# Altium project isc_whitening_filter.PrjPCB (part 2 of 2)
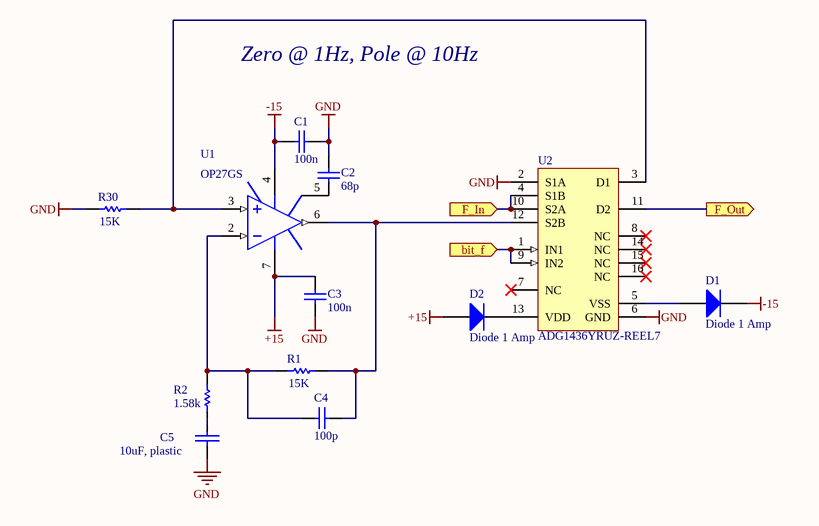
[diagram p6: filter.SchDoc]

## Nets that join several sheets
+15: white_top (25 pins), 24dB_a (C26_24dB_a.2 D7_24dB_a.1 U9_24dB_a.7), 12dB_a (C26_12dB_a.2 D7_12dB_a.1 U9_12dB_a.7), 6dB_a (C26_6dB_a.2 D7_6dB_a.1 U9_6dB_a.7), 3dB_a (C26_3dB_a.2 D7_3dB_a.1 U9_3dB_a.7), U_diff_in_A (C28_U_diff_in_A.1 U10_U_diff_in_A.4), U_diff_out_A (C30_U_diff_out_A.1 U11_U_diff_out_A.8), U_logic_A (U14_U_logic_A.13 U15_U_logic_A.13), U_diff_in_B (C28_U_diff_in_B.1 U10_U_diff_in_B.4), U_diff_out_B (C30_U_diff_out_B.1 U11_U_diff_out_B.8), U_logic_B (U14_U_logic_B.13 U15_U_logic_B.13), U_diff_in_C (C28_U_diff_in_C.1 U10_U_diff_in_C.4), U_diff_out_C (C30_U_diff_out_C.1 U11_U_diff_out_C.8), U_logic_C (U14_U_logic_C.13 U15_U_logic_C.13), U_diff_in_D (C28_U_diff_in_D.1 U10_U_diff_in_D.4), U_diff_out_D (C30_U_diff_out_D.1 U11_U_diff_out_D.8), U_logic_D (U14_U_logic_D.13 U15_U_logic_D.13), 24dB_b (C26_24dB_b.2 D7_24dB_b.1 U9_24dB_b.7), 12dB_b (C26_12dB_b.2 D7_12dB_b.1 U9_12dB_b.7), 12dB_c (C26_12dB_c.2 D7_12dB_c.1 U9_12dB_c.7), 12dB_d (C26_12dB_d.2 D7_12dB_d.1 U9_12dB_d.7), 24dB_c (C26_24dB_c.2 D7_24dB_c.1 U9_24dB_c.7), 24dB_d (C26_24dB_d.2 D7_24dB_d.1 U9_24dB_d.7), 6dB_b (C26_6dB_b.2 D7_6dB_b.1 U9_6dB_b.7), 6dB_c (C26_6dB_c.2 D7_6dB_c.1 U9_6dB_c.7), 6dB_d (C26_6dB_d.2 D7_6dB_d.1 U9_6dB_d.7), 3dB_b (C26_3dB_b.2 D7_3dB_b.1 U9_3dB_b.7), 3dB_c (C26_3dB_c.2 D7_3dB_c.1 U9_3dB_c.7), 3dB_d (C26_3dB_d.2 D7_3dB_d.1 U9_3dB_d.7), PZ1_b (C3_PZ1_b.2 D2_PZ1_b.1 U1_PZ1_b.7), PZ2_b (C3_PZ2_b.2 D2_PZ2_b.1 U1_PZ2_b.7), PZ3_b (C3_PZ3_b.2 D2_PZ3_b.1 U1_PZ3_b.7), PZ1_a (C3_PZ1_a.2 D2_PZ1_a.1 U1_PZ1_a.7), PZ2_a (C3_PZ2_a.2 D2_PZ2_a.1 U1_PZ2_a.7), PZ3_a (C3_PZ3_a.2 D2_PZ3_a.1 U1_PZ3_a.7), PZ1_c (C3_PZ1_c.2 D2_PZ1_c.1 U1_PZ1_c.7), PZ2_c (C3_PZ2_c.2 D2_PZ2_c.1 U1_PZ2_c.7), PZ3_c (C3_PZ3_c.2 D2_PZ3_c.1 U1_PZ3_c.7), PZ1_d (C3_PZ1_d.2 D2_PZ1_d.1 U1_PZ1_d.7), PZ2_d (C3_PZ2_d.2 D2_PZ2_d.1 U1_PZ2_d.7), PZ3_d (C3_PZ3_d.2 D2_PZ3_d.1 U1_PZ3_d.7)
-15: white_top (16 pins), 24dB_a (C24_24dB_a.2 D6_24dB_a.2 U9_24dB_a.4), 12dB_a (C24_12dB_a.2 D6_12dB_a.2 U9_12dB_a.4), 6dB_a (C24_6dB_a.2 D6_6dB_a.2 U9_6dB_a.4), 3dB_a (C24_3dB_a.2 D6_3dB_a.2 U9_3dB_a.4), U_diff_in_A (C29_U_diff_in_A.1 U10_U_diff_in_A.13), U_diff_out_A (C31_U_diff_out_A.1 U11_U_diff_out_A.4), U_logic_A (C32_U_logic_A.2 C36_U_logic_A.2 U14_U_logic_A.4 U15_U_logic_A.4), U_diff_in_B (C29_U_diff_in_B.1 U10_U_diff_in_B.13), U_diff_out_B (C31_U_diff_out_B.1 U11_U_diff_out_B.4), U_logic_B (C32_U_logic_B.2 C36_U_logic_B.2 U14_U_logic_B.4 U15_U_logic_B.4), U_diff_in_C (C29_U_diff_in_C.1 U10_U_diff_in_C.13), U_diff_out_C (C31_U_diff_out_C.1 U11_U_diff_out_C.4), U_logic_C (C32_U_logic_C.2 C36_U_logic_C.2 U14_U_logic_C.4 U15_U_logic_C.4), U_diff_in_D (C29_U_diff_in_D.1 U10_U_diff_in_D.13), U_diff_out_D (C31_U_diff_out_D.1 U11_U_diff_out_D.4), U_logic_D (C32_U_logic_D.2 C36_U_logic_D.2 U14_U_logic_D.4 U15_U_logic_D.4), 24dB_b (C24_24dB_b.2 D6_24dB_b.2 U9_24dB_b.4), 12dB_b (C24_12dB_b.2 D6_12dB_b.2 U9_12dB_b.4), 12dB_c (C24_12dB_c.2 D6_12dB_c.2 U9_12dB_c.4), 12dB_d (C24_12dB_d.2 D6_12dB_d.2 U9_12dB_d.4), 24dB_c (C24_24dB_c.2 D6_24dB_c.2 U9_24dB_c.4), 24dB_d (C24_24dB_d.2 D6_24dB_d.2 U9_24dB_d.4), 6dB_b (C24_6dB_b.2 D6_6dB_b.2 U9_6dB_b.4), 6dB_c (C24_6dB_c.2 D6_6dB_c.2 U9_6dB_c.4), 6dB_d (C24_6dB_d.2 D6_6dB_d.2 U9_6dB_d.4), 3dB_b (C24_3dB_b.2 D6_3dB_b.2 U9_3dB_b.4), 3dB_c (C24_3dB_c.2 D6_3dB_c.2 U9_3dB_c.4), 3dB_d (C24_3dB_d.2 D6_3dB_d.2 U9_3dB_d.4), PZ1_b (C1_PZ1_b.2 D1_PZ1_b.2 U1_PZ1_b.4), PZ2_b (C1_PZ2_b.2 D1_PZ2_b.2 U1_PZ2_b.4), PZ3_b (C1_PZ3_b.2 D1_PZ3_b.2 U1_PZ3_b.4), PZ1_a (C1_PZ1_a.2 D1_PZ1_a.2 U1_PZ1_a.4), PZ2_a (C1_PZ2_a.2 D1_PZ2_a.2 U1_PZ2_a.4), PZ3_a (C1_PZ3_a.2 D1_PZ3_a.2 U1_PZ3_a.4), PZ1_c (C1_PZ1_c.2 D1_PZ1_c.2 U1_PZ1_c.4), PZ2_c (C1_PZ2_c.2 D1_PZ2_c.2 U1_PZ2_c.4), PZ3_c (C1_PZ3_c.2 D1_PZ3_c.2 U1_PZ3_c.4), PZ1_d (C1_PZ1_d.2 D1_PZ1_d.2 U1_PZ1_d.4), PZ2_d (C1_PZ2_d.2 D1_PZ2_d.2 U1_PZ2_d.4), PZ3_d (C1_PZ3_d.2 D1_PZ3_d.2 U1_PZ3_d.4)
GND: white_top (38 pins), 24dB_a (7 pins), 12dB_a (7 pins), 6dB_a (7 pins), 3dB_a (7 pins), U_diff_in_A (7 pins), U_diff_out_A (C30_U_diff_out_A.2 C31_U_diff_out_A.2 U11_U_diff_out_A.5), U_logic_A (15 pins), U_diff_in_B (7 pins), U_diff_out_B (C30_U_diff_out_B.2 C31_U_diff_out_B.2 U11_U_diff_out_B.5), U_logic_B (15 pins), U_diff_in_C (7 pins), U_diff_out_C (C30_U_diff_out_C.2 C31_U_diff_out_C.2 U11_U_diff_out_C.5), U_logic_C (15 pins), U_diff_in_D (7 pins), U_diff_out_D (C30_U_diff_out_D.2 C31_U_diff_out_D.2 U11_U_diff_out_D.5), U_logic_D (15 pins), 24dB_b (7 pins), 12dB_b (7 pins), 12dB_c (7 pins), 12dB_d (7 pins), 24dB_c (7 pins), 24dB_d (7 pins), 6dB_b (7 pins), 6dB_c (7 pins), 6dB_d (7 pins), 3dB_b (7 pins), 3dB_c (7 pins), 3dB_d (7 pins), PZ1_b (7 pins), PZ2_b (7 pins), PZ3_b (7 pins), PZ1_a (7 pins), PZ2_a (7 pins), PZ3_a (7 pins), PZ1_c (7 pins), PZ2_c (7 pins), PZ3_c (7 pins), PZ1_d (7 pins), PZ2_d (7 pins), PZ3_d (7 pins)
VCC: white_top (5 pins), U_logic_A (5 pins), U_logic_B (5 pins), U_logic_C (5 pins), U_logic_D (5 pins)
A1: 24dB_a (U8_24dB_a.1 U8_24dB_a.9), U_logic_A (U13_U_logic_A.19 U14_U_logic_A.1)
A2: 12dB_a (U8_12dB_a.1 U8_12dB_a.9), U_logic_A (U13_U_logic_A.18 U14_U_logic_A.16)
A3: 6dB_a (U8_6dB_a.1 U8_6dB_a.9), U_logic_A (U13_U_logic_A.17 U14_U_logic_A.9)
A4: 3dB_a (U8_3dB_a.1 U8_3dB_a.9), U_logic_A (U13_U_logic_A.16 U14_U_logic_A.8)
A5: U_logic_A (U13_U_logic_A.15 U15_U_logic_A.1), PZ1_a (U2_PZ1_a.1 U2_PZ1_a.9)
A6: U_logic_A (U13_U_logic_A.14 U15_U_logic_A.16), PZ2_a (U2_PZ2_a.1 U2_PZ2_a.9)
A7: U_logic_A (U13_U_logic_A.13 U15_U_logic_A.9), PZ3_a (U2_PZ3_a.1 U2_PZ3_a.9)
AN_1: white_top (IN1.2 J5.9), U_diff_in_A (R22_U_diff_in_A.1 R33_U_diff_in_A.2)
AN_2: white_top (IN2.2 J5.10), U_diff_in_B (R22_U_diff_in_B.1 R33_U_diff_in_B.2)
AN_3: white_top (IN3.2 J5.11), U_diff_in_C (R22_U_diff_in_C.1 R33_U_diff_in_C.2)
AN_4: white_top (IN4.2 J5.12), U_diff_in_D (R22_U_diff_in_D.1 R33_U_diff_in_D.2)
AP_1: white_top (IN1.1 J5.1), U_diff_in_A (R14_U_diff_in_A.2 R32_U_diff_in_A.2)
AP_2: white_top (IN2.1 J5.2), U_diff_in_B (R14_U_diff_in_B.2 R32_U_diff_in_B.2)
AP_3: white_top (IN3.1 J5.3), U_diff_in_C (R14_U_diff_in_C.2 R32_U_diff_in_C.2)
AP_4: white_top (IN4.1 J5.4), U_diff_in_D (R14_U_diff_in_D.2 R32_U_diff_in_D.2)
B1: U_logic_B (U13_U_logic_B.19 U14_U_logic_B.1), 24dB_b (U8_24dB_b.1 U8_24dB_b.9)
B2: U_logic_B (U13_U_logic_B.18 U14_U_logic_B.16), 12dB_b (U8_12dB_b.1 U8_12dB_b.9)
B3: U_logic_B (U13_U_logic_B.17 U14_U_logic_B.9), 6dB_b (U8_6dB_b.1 U8_6dB_b.9)
B4: U_logic_B (U13_U_logic_B.16 U14_U_logic_B.8), 3dB_b (U8_3dB_b.1 U8_3dB_b.9)
B5: U_logic_B (U13_U_logic_B.15 U15_U_logic_B.1), PZ1_b (U2_PZ1_b.1 U2_PZ1_b.9)
B6: U_logic_B (U13_U_logic_B.14 U15_U_logic_B.16), PZ2_b (U2_PZ2_b.1 U2_PZ2_b.9)
B7: U_logic_B (U13_U_logic_B.13 U15_U_logic_B.9), PZ3_b (U2_PZ3_b.1 U2_PZ3_b.9)
BI_0: white_top (P1.2 P2.3), U_logic_A (R29_U_logic_A.3 U13_U_logic_A.2)
BI_1: white_top (P1.3 P2.5), U_logic_A (R29_U_logic_A.4 U13_U_logic_A.3)
BI_2: white_top (P1.4 P2.7), U_logic_A (R29_U_logic_A.5 U13_U_logic_A.4)
BI_3: white_top (P1.5 P2.9), U_logic_A (R29_U_logic_A.6 U13_U_logic_A.5)
BI_4: white_top (P1.6 P2.11), U_logic_A (R29_U_logic_A.7 U13_U_logic_A.6)
BI_5: white_top (P1.7 P2.13), U_logic_A (R29_U_logic_A.8 U13_U_logic_A.7)
BI_6: white_top (P1.8 P2.15), U_logic_A (R29_U_logic_A.9 U13_U_logic_A.8)
BI_7: white_top (P1.9 P2.17), U_logic_A (R29_U_logic_A.2 U13_U_logic_A.11 U15_U_logic_A.8)
BI_8: white_top (P1.10 P2.19), U_logic_B (R29_U_logic_B.3 U13_U_logic_B.2)
BI_9: white_top (P1.11 P2.21), U_logic_B (R29_U_logic_B.4 U13_U_logic_B.3)
BI_10: white_top (P1.12 P2.23), U_logic_B (R29_U_logic_B.5 U13_U_logic_B.4)
BI_11: white_top (P1.13 P2.25), U_logic_B (R29_U_logic_B.6 U13_U_logic_B.5)
BI_12: white_top (P1.14 P2.27), U_logic_B (R29_U_logic_B.7 U13_U_logic_B.6)
BI_13: white_top (P1.15 P2.29), U_logic_B (R29_U_logic_B.8 U13_U_logic_B.7)
BI_14: white_top (P1.16 P2.31), U_logic_B (R29_U_logic_B.9 U13_U_logic_B.8)
BI_15: white_top (P1.17 P2.33), U_logic_B (R29_U_logic_B.2 U13_U_logic_B.11 U15_U_logic_B.8)
BI_16: white_top (P1.21 P2.4), U_logic_C (R29_U_logic_C.3 U13_U_logic_C.2)
BI_17: white_top (P1.22 P2.6), U_logic_C (R29_U_logic_C.4 U13_U_logic_C.3)
BI_18: white_top (P1.23 P2.8), U_logic_C (R29_U_logic_C.5 U13_U_logic_C.4)
BI_19: white_top (P1.24 P2.10), U_logic_C (R29_U_logic_C.6 U13_U_logic_C.5)
BI_20: white_top (P1.25 P2.12), U_logic_C (R29_U_logic_C.7 U13_U_logic_C.6)
BI_21: white_top (P1.26 P2.14), U_logic_C (R29_U_logic_C.8 U13_U_logic_C.7)
BI_22: white_top (P1.27 P2.16), U_logic_C (R29_U_logic_C.9 U13_U_logic_C.8)
BI_23: white_top (P1.28 P2.18), U_logic_C (R29_U_logic_C.2 U13_U_logic_C.11 U15_U_logic_C.8)
BI_24: white_top (P1.29 P2.20), U_logic_D (R29_U_logic_D.3 U13_U_logic_D.2)
BI_25: white_top (P1.30 P2.22), U_logic_D (R29_U_logic_D.4 U13_U_logic_D.3)
BI_26: white_top (P1.31 P2.24), U_logic_D (R29_U_logic_D.5 U13_U_logic_D.4)
BI_27: white_top (P1.32 P2.26), U_logic_D (R29_U_logic_D.6 U13_U_logic_D.5)
BI_28: white_top (P1.33 P2.28), U_logic_D (R29_U_logic_D.7 U13_U_logic_D.6)
BI_29: white_top (P1.34 P2.30), U_logic_D (R29_U_logic_D.8 U13_U_logic_D.7)
BI_30: white_top (P1.35 P2.32), U_logic_D (R29_U_logic_D.9 U13_U_logic_D.8)
BI_31: white_top (P1.36 P2.34), U_logic_D (R29_U_logic_D.2 U13_U_logic_D.11 U15_U_logic_D.8)
BO_0: white_top (P3.2), U_logic_A (R31_U_logic_A.16)
BO_1: white_top (P3.3), U_logic_A (R31_U_logic_A.15)
BO_2: white_top (P3.4), U_logic_A (R31_U_logic_A.14)
BO_3: white_top (P3.5), U_logic_A (R31_U_logic_A.13)
BO_4: white_top (P3.6), U_logic_A (R31_U_logic_A.12)
BO_5: white_top (P3.7), U_logic_A (R31_U_logic_A.11)
BO_6: white_top (P3.8), U_logic_A (R31_U_logic_A.10)
BO_7: white_top (P3.9), U_logic_A (R31_U_logic_A.9)
BO_8: white_top (P3.10), U_logic_B (R31_U_logic_B.16)
BO_9: white_top (P3.11), U_logic_B (R31_U_logic_B.15)
BO_10: white_top (P3.12), U_logic_B (R31_U_logic_B.14)
BO_11: white_top (P3.13), U_logic_B (R31_U_logic_B.13)
BO_12: white_top (P3.14), U_logic_B (R31_U_logic_B.12)
BO_13: white_top (P3.15), U_logic_B (R31_U_logic_B.11)
BO_14: white_top (P3.16), U_logic_B (R31_U_logic_B.10)
BO_15: white_top (P3.17), U_logic_B (R31_U_logic_B.9)
BO_16: white_top (P3.21), U_logic_C (R31_U_logic_C.16)
BO_17: white_top (P3.22), U_logic_C (R31_U_logic_C.15)
BO_18: white_top (P3.23), U_logic_C (R31_U_logic_C.14)
BO_19: white_top (P3.24), U_logic_C (R31_U_logic_C.13)
BO_20: white_top (P3.25), U_logic_C (R31_U_logic_C.12)
BO_21: white_top (P3.26), U_logic_C (R31_U_logic_C.11)
BO_22: white_top (P3.27), U_logic_C (R31_U_logic_C.10)
BO_23: white_top (P3.28), U_logic_C (R31_U_logic_C.9)
BO_24: white_top (P3.29), U_logic_D (R31_U_logic_D.16)
BO_25: white_top (P3.30), U_logic_D (R31_U_logic_D.15)
BO_26: white_top (P3.31), U_logic_D (R31_U_logic_D.14)
BO_27: white_top (P3.32), U_logic_D (R31_U_logic_D.13)
BO_28: white_top (P3.33), U_logic_D (R31_U_logic_D.12)
BO_29: white_top (P3.34), U_logic_D (R31_U_logic_D.11)
BO_30: white_top (P3.35), U_logic_D (R31_U_logic_D.10)
BO_31: white_top (P3.36), U_logic_D (R31_U_logic_D.9)
C1: U_logic_C (U13_U_logic_C.19 U14_U_logic_C.1), 24dB_c (U8_24dB_c.1 U8_24dB_c.9)
C2: U_logic_C (U13_U_logic_C.18 U14_U_logic_C.16), 12dB_c (U8_12dB_c.1 U8_12dB_c.9)
C3: U_logic_C (U13_U_logic_C.17 U14_U_logic_C.9), 6dB_c (U8_6dB_c.1 U8_6dB_c.9)
C4: U_logic_C (U13_U_logic_C.16 U14_U_logic_C.8), 3dB_c (U8_3dB_c.1 U8_3dB_c.9)
C5: U_logic_C (U13_U_logic_C.15 U15_U_logic_C.1), PZ1_c (U2_PZ1_c.1 U2_PZ1_c.9)
C6: U_logic_C (U13_U_logic_C.14 U15_U_logic_C.16), PZ2_c (U2_PZ2_c.1 U2_PZ2_c.9)
C7: U_logic_C (U13_U_logic_C.13 U15_U_logic_C.9), PZ3_c (U2_PZ3_c.1 U2_PZ3_c.9)
D1: U_logic_D (U13_U_logic_D.19 U14_U_logic_D.1), 24dB_d (U8_24dB_d.1 U8_24dB_d.9)
D2: U_logic_D (U13_U_logic_D.18 U14_U_logic_D.16), 12dB_d (U8_12dB_d.1 U8_12dB_d.9)
D3: U_logic_D (U13_U_logic_D.17 U14_U_logic_D.9), 6dB_d (U8_6dB_d.1 U8_6dB_d.9)
D4: U_logic_D (U13_U_logic_D.16 U14_U_logic_D.8), 3dB_d (U8_3dB_d.1 U8_3dB_d.9)
D5: U_logic_D (U13_U_logic_D.15 U15_U_logic_D.1), PZ1_d (U2_PZ1_d.1 U2_PZ1_d.9)
D6: U_logic_D (U13_U_logic_D.14 U15_U_logic_D.16), PZ2_d (U2_PZ2_d.1 U2_PZ2_d.9)
D7: U_logic_D (U13_U_logic_D.13 U15_U_logic_D.9), PZ3_d (U2_PZ3_d.1 U2_PZ3_d.9)
NetC39_U_diff_in_A_2: white_top (TP1.1), 24dB_a (U8_24dB_a.4 U8_24dB_a.10), U_diff_in_A (C39_U_diff_in_A.2 R20_U_diff_in_A.1 U10_U_diff_in_A.10)
NetC39_U_diff_in_B_2: white_top (TP14.1), U_diff_in_B (C39_U_diff_in_B.2 R20_U_diff_in_B.1 U10_U_diff_in_B.10), 24dB_b (U8_24dB_b.4 U8_24dB_b.10)
NetC39_U_diff_in_C_2: white_top (TP17.1), U_diff_in_C (C39_U_diff_in_C.2 R20_U_diff_in_C.1 U10_U_diff_in_C.10), 24dB_c (U8_24dB_c.4 U8_24dB_c.10)
NetC39_U_diff_in_D_2: white_top (TP20.1), U_diff_in_D (C39_U_diff_in_D.2 R20_U_diff_in_D.1 U10_U_diff_in_D.10), 24dB_d (U8_24dB_d.4 U8_24dB_d.10)
NetR3_2: white_top (R3.2 U3.6), U_diff_out_A (R24_U_diff_out_A.1 R27_U_diff_out_A.1 TP8_U_diff_out_A.1 U11_U_diff_out_A.3)
NetR4_2: white_top (R4.2 U4.6), U_diff_out_B (R24_U_diff_out_B.1 R27_U_diff_out_B.1 TP8_U_diff_out_B.1 U11_U_diff_out_B.3)
NetR5_2: white_top (R5.2 U5.6), U_diff_out_C (R24_U_diff_out_C.1 R27_U_diff_out_C.1 TP8_U_diff_out_C.1 U11_U_diff_out_C.3)
NetR6_2: white_top (R6.2 U6.6), U_diff_out_D (R24_U_diff_out_D.1 R27_U_diff_out_D.1 TP8_U_diff_out_D.1 U11_U_diff_out_D.3)
NetTP2_1: white_top (TP2.1), 3dB_a (U8_3dB_a.11), PZ1_a (U2_PZ1_a.4 U2_PZ1_a.10)
NetTP13_1: white_top (TP13.1 U3.3), PZ3_a (U2_PZ3_a.11)
NetTP15_1: white_top (TP15.1), 3dB_b (U8_3dB_b.11), PZ1_b (U2_PZ1_b.4 U2_PZ1_b.10)
NetTP16_1: white_top (TP16.1 U4.3), PZ3_b (U2_PZ3_b.11)
NetTP18_1: white_top (TP18.1), 3dB_c (U8_3dB_c.11), PZ1_c (U2_PZ1_c.4 U2_PZ1_c.10)
NetTP19_1: white_top (TP19.1 U5.3), PZ3_c (U2_PZ3_c.11)
NetTP21_1: white_top (TP21.1), 3dB_d (U8_3dB_d.11), PZ1_d (U2_PZ1_d.4 U2_PZ1_d.10)
NetTP22_1: white_top (TP22.1 U6.3), PZ3_d (U2_PZ3_d.11)
NetU2_PZ1_a_11: PZ1_a (U2_PZ1_a.11), PZ2_a (U2_PZ2_a.4 U2_PZ2_a.10)
NetU2_PZ1_b_11: PZ1_b (U2_PZ1_b.11), PZ2_b (U2_PZ2_b.4 U2_PZ2_b.10)
NetU2_PZ1_c_11: PZ1_c (U2_PZ1_c.11), PZ2_c (U2_PZ2_c.4 U2_PZ2_c.10)
NetU2_PZ1_d_11: PZ1_d (U2_PZ1_d.11), PZ2_d (U2_PZ2_d.4 U2_PZ2_d.10)
NetU2_PZ2_a_11: PZ2_a (U2_PZ2_a.11), PZ3_a (U2_PZ3_a.4 U2_PZ3_a.10)
NetU2_PZ2_b_11: PZ2_b (U2_PZ2_b.11), PZ3_b (U2_PZ3_b.4 U2_PZ3_b.10)
NetU2_PZ2_c_11: PZ2_c (U2_PZ2_c.11), PZ3_c (U2_PZ3_c.4 U2_PZ3_c.10)
NetU2_PZ2_d_11: PZ2_d (U2_PZ2_d.11), PZ3_d (U2_PZ3_d.4 U2_PZ3_d.10)
NetU8_3dB_a_4: 6dB_a (U8_6dB_a.11), 3dB_a (U8_3dB_a.4 U8_3dB_a.10)
NetU8_3dB_b_4: 6dB_b (U8_6dB_b.11), 3dB_b (U8_3dB_b.4 U8_3dB_b.10)
NetU8_3dB_c_4: 6dB_c (U8_6dB_c.11), 3dB_c (U8_3dB_c.4 U8_3dB_c.10)
NetU8_3dB_d_4: 6dB_d (U8_6dB_d.11), 3dB_d (U8_3dB_d.4 U8_3dB_d.10)
NetU8_6dB_a_4: 12dB_a (U8_12dB_a.11), 6dB_a (U8_6dB_a.4 U8_6dB_a.10)
NetU8_6dB_b_4: 12dB_b (U8_12dB_b.11), 6dB_b (U8_6dB_b.4 U8_6dB_b.10)
NetU8_6dB_c_4: 12dB_c (U8_12dB_c.11), 6dB_c (U8_6dB_c.4 U8_6dB_c.10)
NetU8_6dB_d_4: 12dB_d (U8_12dB_d.11), 6dB_d (U8_6dB_d.4 U8_6dB_d.10)
NetU8_12dB_a_4: 24dB_a (U8_24dB_a.11), 12dB_a (U8_12dB_a.4 U8_12dB_a.10)
NetU8_12dB_b_4: 24dB_b (U8_24dB_b.11), 12dB_b (U8_12dB_b.4 U8_12dB_b.10)
NetU8_12dB_c_4: 12dB_c (U8_12dB_c.4 U8_12dB_c.10), 24dB_c (U8_24dB_c.11)
NetU8_12dB_d_4: 12dB_d (U8_12dB_d.4 U8_12dB_d.10), 24dB_d (U8_24dB_d.11)
WN1: white_top (J6.6 OUT1.2), U_diff_out_A (R26_U_diff_out_A.2)
WN2: white_top (J6.7 OUT2.2), U_diff_out_B (R26_U_diff_out_B.2)
WN3: white_top (J6.8 OUT3.2), U_diff_out_C (R26_U_diff_out_C.2)
WN4: white_top (J6.9 OUT4.2), U_diff_out_D (R26_U_diff_out_D.2)
WP1: white_top (J6.1 OUT1.1), U_diff_out_A (R23_U_diff_out_A.2)
WP2: white_top (J6.2 OUT2.1), U_diff_out_B (R23_U_diff_out_B.2)
WP3: white_top (J6.3 OUT3.1), U_diff_out_C (R23_U_diff_out_C.2)
WP4: white_top (J6.4 OUT4.1), U_diff_out_D (R23_U_diff_out_D.2)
